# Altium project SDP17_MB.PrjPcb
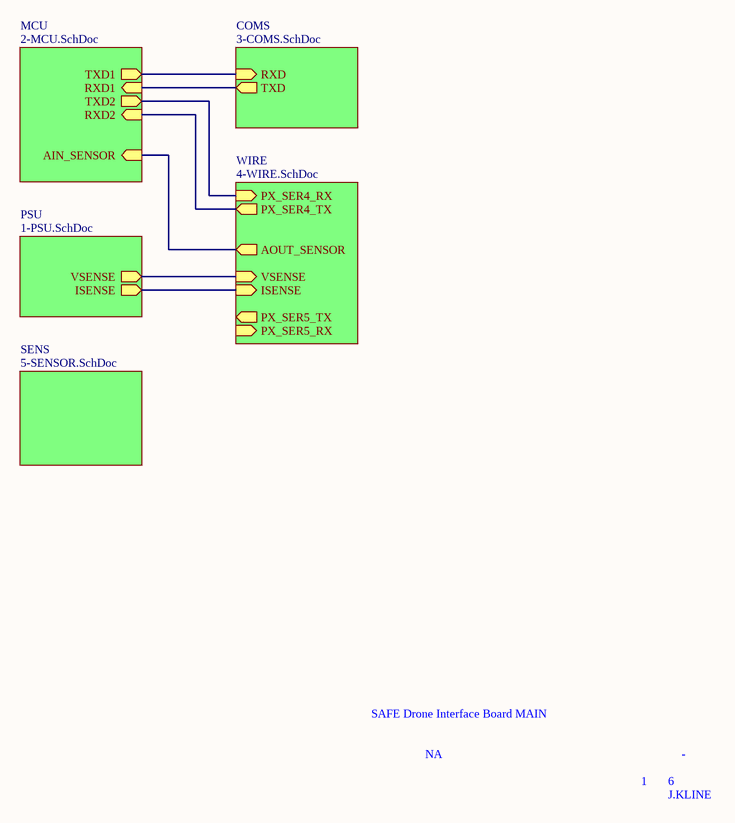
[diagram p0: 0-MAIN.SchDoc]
6 sheets, 82 parts. Net scope: hierarchical (ports join the sheet entries above them; power ports are global).
Board file: MB_rev0.PcbDoc
Sheets:
  0-MAIN.SchDoc
    MCU = 2-MCU.SchDoc
    COMS = 3-COMS.SchDoc
    PSU = 1-PSU.SchDoc
    WIRE = 4-WIRE.SchDoc
    SENS = 5-SENSOR.SchDoc

## Sheet 0-MAIN.SchDoc
size A

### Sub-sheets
COMS = 3-COMS.SchDoc: TXD (out), RXD (in)
MCU = 2-MCU.SchDoc: TXD1 (out), RXD1 (in), TXD2 (out), RXD2 (in), AIN_SENSOR (in)
PSU = 1-PSU.SchDoc: VSENSE (out), ISENSE (out)
SENS = 5-SENSOR.SchDoc: no entries
WIRE = 4-WIRE.SchDoc: PX_SER4_RX (in), PX_SER4_TX (out), PX_SER5_TX (out), PX_SER5_RX (in), ISENSE (in), VSENSE (in), AOUT_SENSOR (out)

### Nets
AIN_SENSOR: sheet MCU/AIN_SENSOR, sheet WIRE/AOUT_SENSOR
RXD1: sheet MCU/RXD1, sheet COMS/TXD
RXD2: sheet MCU/RXD2, sheet WIRE/PX_SER4_TX
TXD1: sheet MCU/TXD1, sheet COMS/RXD
TXD2: sheet MCU/TXD2, sheet WIRE/PX_SER4_RX
NetC18_1: sheet PSU/VSENSE, sheet WIRE/VSENSE
NetC19_1: sheet PSU/ISENSE, sheet WIRE/ISENSE

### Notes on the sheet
- SAFE Drone Interface Board MAIN
- NA
- 1
- 6
- -
- J.KLINE

## Sheet 2-MCU.SchDoc
size A3; DrawnBy: Jamie Kline; Organization: UMASS ECE
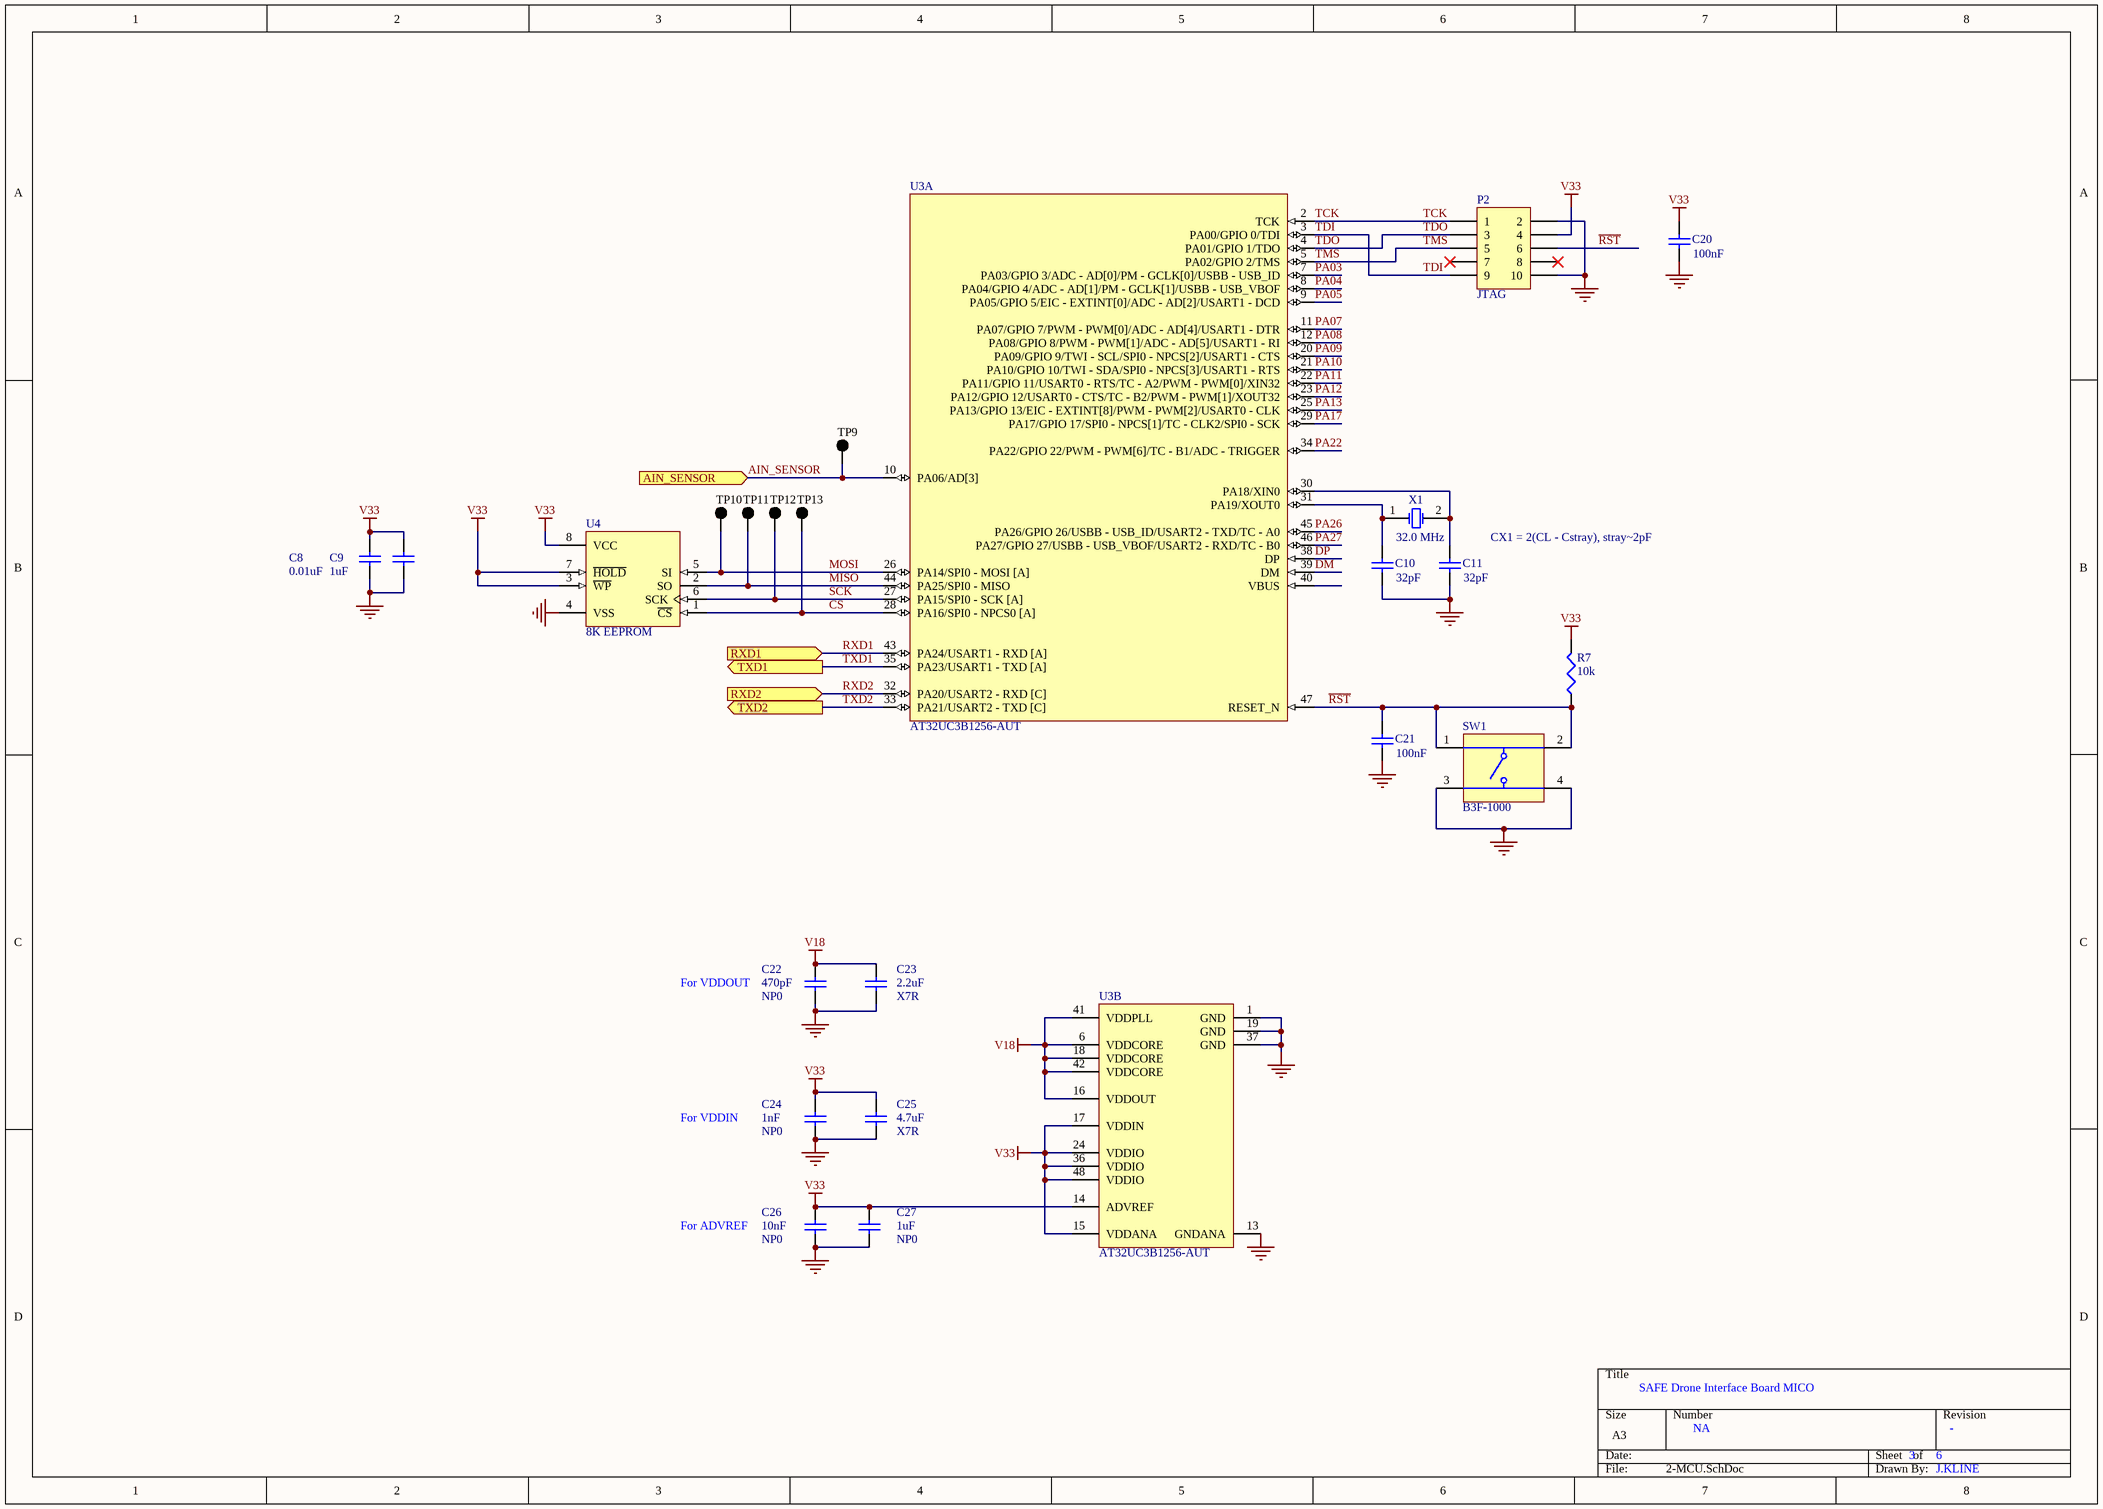
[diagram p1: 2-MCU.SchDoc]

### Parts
(Parts that share a designator on the sheet are numbered #1, #2 ... from top to bottom, then left to right.)
C8  value 0.01uF  [1608[0603]]  (hidden comment: Cap Semi)
C9  value 1uF  [1608[0603]]  (hidden comment: Cap Semi)
C10  value 32pF  [1608[0603]]  (hidden comment: Cap Semi)
C11  value 32pF  [1608[0603]]  (hidden comment: Cap Semi)
C20  value 100nF  [1608[0603]]  (hidden comment: Cap Semi)
C21  value 100nF  [1608[0603]]  (hidden comment: Cap Semi)
C22  value 470pF  Tempco: NP0  [1608[0603]]  (hidden comment: Cap Semi)
C23  value 2.2uF  Tempco: X7R  [1608[0603]]
C24  value 1nF  Tempco: NP0  [1608[0603]]  (hidden comment: Cap Semi)
C25  value 4.7uF  Tempco: X7R  [1608[0603]]
C26  value 10nF  Tempco: NP0  [1608[0603]]  (hidden comment: Cap Semi)
C27  value 1uF  Tempco: NP0  [1608[0603]]  (hidden comment: Cap Semi)
P2  JTAG  [HDR2X5]
R7  value 10k  [J1-0603]  (hidden comment: Res3)
SW1  B3F-1000  [OMRON-B3F-1000-4_V]
TP9#1  SENSOR  [KSTN-5011_V]  (value not drawn)
TP10  MOSI  [KSTN-5011_V]  (value not drawn)
TP11  MISO  [KSTN-5011_V]  (value not drawn)
TP12  SCK  [KSTN-5011_V]  (value not drawn)
TP13  CS  [KSTN-5011_V]  (value not drawn)
U3  AT32UC3B1256-AUT  [TQFP48_N]  (parts A,B of 2)
U4  8K EEPROM  [SOIC-SN8_N]
X1  Frequency: 32.0 MHz  [ABRA-ABLS2-2_V]  (hidden comment: ABLS2-32.000MHZ-D4YF-T)

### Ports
AIN_SENSOR (in), RXD1 (in), RXD2 (in), TXD1 (out), TXD2 (out)

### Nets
GND: C8.1 C9.2 C10.1 C11.1 C20.1 C21.1 C22.2 C23.1 C24.2 C25.1 C26.2 C27.2 P2.2 P2.10 SW1.3 SW1.4 U3.1(GND) U3.13(GNDANA) U3.19(GND) U3.37(GND) U4.4(VSS)
V18: C22.1 C23.2 U3.6(VDDCORE) U3.16(VDDOUT) U3.18(VDDCORE) U3.41(VDDPLL) U3.42(VDDCORE)
V33: C8.2 C9.1 C20.2 C24.1 C25.2 C26.1 C27.1 P2.4 R7.2 U3.14(ADVREF) U3.15(VDDANA) U3.17(VDDIN) U3.24(VDDIO) U3.36(VDDIO) U3.48(VDDIO) U4.3(~{WP}) U4.7(~{HOLD}) U4.8(VCC)
AIN_SENSOR: TP9#1.1 U3.10(PA06/AD[3]) ; port AIN_SENSOR
CS: TP13.1 U3.28(PA16/SPI0_-_NPCS0_[A]) U4.1(~{CS})
DM: U3.39(DM)
DP: U3.38(DP)
MISO: TP11.1 U3.44(PA25/SPI0_-_MISO) U4.2(SO)
MOSI: TP10.1 U3.26(PA14/SPI0_-_MOSI_[A]) U4.5(SI)
PA03: U3.7(PA03/GPIO_3/ADC_-_AD[0]/PM_-_GCLK[0]/USBB_-_USB_ID)
PA04: U3.8(PA04/GPIO_4/ADC_-_AD[1]/PM_-_GCLK[1]/USBB_-_USB_VBOF)
PA05: U3.9(PA05/GPIO_5/EIC_-_EXTINT[0]/ADC_-_AD[2]/USART1_-_DCD)
PA07: U3.11(PA07/GPIO_7/PWM_-_PWM[0]/ADC_-_AD[4]/USART1_-_DTR)
PA08: U3.12(PA08/GPIO_8/PWM_-_PWM[1]/ADC_-_AD[5]/USART1_-_RI)
PA09: U3.20(PA09/GPIO_9/TWI_-_SCL/SPI0_-_NPCS[2]/USART1_-_CTS)
PA10: U3.21(PA10/GPIO_10/TWI_-_SDA/SPI0_-_NPCS[3]/USART1_-_RTS)
PA11: U3.22(PA11/GPIO_11/USART0_-_RTS/TC_-_A2/PWM_-_PWM[0]/XIN32)
PA12: U3.23(PA12/GPIO_12/USART0_-_CTS/TC_-_B2/PWM_-_PWM[1]/XOUT32)
PA13: U3.25(PA13/GPIO_13/EIC_-_EXTINT[8]/PWM_-_PWM[2]/USART0_-_CLK)
PA17: U3.29(PA17/GPIO_17/SPI0_-_NPCS[1]/TC_-_CLK2/SPI0_-_SCK)
PA22: U3.34(PA22/GPIO_22/PWM_-_PWM[6]/TC_-_B1/ADC_-_TRIGGER)
PA26: U3.45(PA26/GPIO_26/USBB_-_USB_ID/USART2_-_TXD/TC_-_A0)
PA27: U3.46(PA27/GPIO_27/USBB_-_USB_VBOF/USART2_-_RXD/TC_-_B0)
~{RST}: C21.2 P2.6 R7.1 SW1.1 SW1.2 U3.47(RESET_N)
RXD1: U3.43(PA24/USART1_-_RXD_[A]) ; port RXD1
RXD2: U3.32(PA20/USART2_-_RXD_[C]) ; port RXD2
SCK: TP12.1 U3.27(PA15/SPI0_-_SCK_[A]) U4.6(SCK)
TCK: P2.1 U3.2(TCK)
TDI: P2.9 U3.3(PA00/GPIO_0/TDI)
TDO: P2.3 U3.4(PA01/GPIO_1/TDO)
TMS: P2.5 U3.5(PA02/GPIO_2/TMS)
TXD1: U3.35(PA23/USART1_-_TXD_[A]) ; port TXD1
TXD2: U3.33(PA21/USART2_-_TXD_[C]) ; port TXD2
NetC10_2: C10.2 U3.31(PA19/XOUT0) X1.1(X1)
NetC11_2: C11.2 U3.30(PA18/XIN0) X1.2(X2)

Not connected (* = marked no-connect by the designer): P2 7* 8*; U3 40(VBUS)

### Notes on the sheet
- (near C11) CX1 = 2(CL - Cstray), stray|pF
- For VDDOUT
- For VDDIN
- For ADVREF
- SAFE Drone Interface Board MICO
- NA
- 3
- 6
- -
- J.KLINE

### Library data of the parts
C8-C11 C20-C22 C24 C26 C27 = Cap Semi: Capacitor (Semiconductor SIM Model)
C23 C25 = Cap SMT: Capacitor (Semiconductor SIM Model)
P2 = Header 5X2: Header, 5-Pin, Dual row
R7 = Res3: Resistor
SW1 = CMP-1677-00002-1: Tactile Switch, SPST-NO, 0.05 A, 5 to 24 V, -25 to 70 degC, 4-Pin THD, RoHS, Bulk; Shielding: Shielded; Gender: Female; Capacitance: -45 f; Voltage Rating: 150 V; Current Rating: 1.5 A
TP9#1 TP10-TP13 = CMP-1672-00003-4: Test Point, Black, Through Hole, RoHS, Bulk; Manufacturer: Keystone
U3 = AT32UC3B1256-AUT: 32-bit AVR UC3 B Series Microcontroller, 256KB Flash, 32KB SRAM, 28 GPIO pins, Industrial Grade, 48-Pin TQFP, Tray
U4 = CMP-0165-00135-1: 8K SPI Bus Serial EEPROM, 8-Pin SOIC, Tape and Reel; Manufacture PN: CAT25080VI-GT3; ComponentAvailability: Unknown. Contact manufacturer to determine status.
X1 = CMP-0277-00002-1: Low Profile Surface Mount Microprocessor Crystal, 4.096 MHz +/-30 ppm, 180 Ohm, -40 to 85 degC, 2-Pin 11.4 x 4.7 x 3.3 mm SMD, RoHS, Tape and Reel; Manufacturer: Abracon; Operation Mode: Fundamental or 3rd Overtone; Shunt Capacitance: 7 pF Max.; ESR: 180 Ohm; Load Capacitance: 18 pF

## Sheet 3-COMS.SchDoc
size A
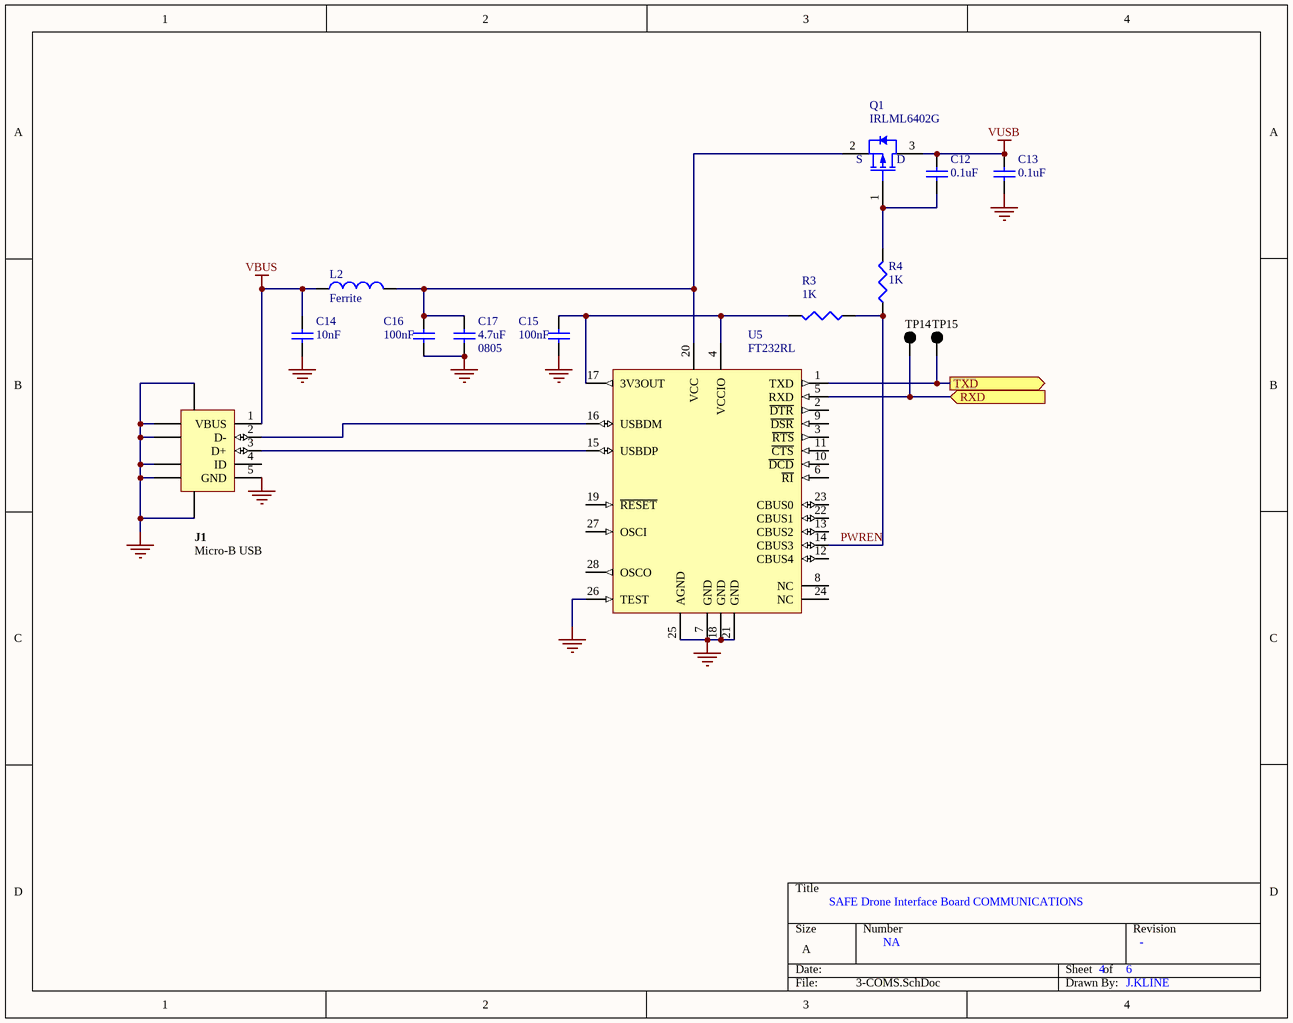
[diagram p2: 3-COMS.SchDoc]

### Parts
C12  value 0.1uF  [1608[0603]]  (hidden comment: Cap Semi)
C13  value 0.1uF  [1608[0603]]  (hidden comment: Cap Semi)
C14  value 10nF  [1608[0603]]  (hidden comment: Cap Semi)
C15  value 100nF  [1608[0603]]  (hidden comment: Cap Semi)
C16  value 100nF  [1608[0603]]  (hidden comment: Cap Semi)
C17  0805  value 4.7uF  [2012[0805]]
J1  Micro-B USB  [HIRO-ZX62R-B-5P_V]
L2  Ferrite  [INDC2013X105X50ML20T30]
Q1  IRLML6402G  [INTR-SOT-23-3_V]
R3  value 1K  [J1-0603]  (hidden comment: Res3)
R4  value 1K  [J1-0603]  (hidden comment: Res3)
TP14  RX  [KSTN-5011_V]  (value not drawn)
TP15  TX  [KSTN-5011_V]  (value not drawn)
U5  FT232RL  [SSOP-28_N]

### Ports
RXD (in), TXD (out)

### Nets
GND: C13.1 C14.1 C15.2 C16.1 C17.1 J1.5(GND) J1.6(SHLD) J1.7(SHLD) J1.8(SHLD) J1.9(SHLD) J1.10(SHLD) J1.11(SHLD) U5.7(GND) U5.18(GND) U5.21(GND) U5.25(AGND) U5.26(TEST)
VBUS: C14.2 J1.1(VBUS) L2.1
VUSB: C12.2 C13.2 Q1.3(D)
PWREN: R3.1 R4.1 U5.14(CBUS3)
RXD1: TP15.1 U5.1(TXD) ; port TXD
TXD1: TP14.1 U5.5(RXD) ; port RXD
NetC12_1: C12.1 Q1.1(G) R4.2
NetC15_1: C15.1 R3.2 U5.4(VCCIO) U5.17(3V3OUT)
NetC16_2: C16.2 C17.2 L2.2 Q1.2(S) U5.20(VCC)
NetJ1_2: J1.2(D-) U5.16(USBDM)
NetJ1_3: J1.3(D+) U5.15(USBDP)

Not connected (* = marked no-connect by the designer): J1 4(ID); U5 2(~{DTR}) 3(~{RTS}) 6(~{RI}) 8(NC) 9(~{DSR}) 10(~{DCD}) 11(~{CTS}) 12(CBUS4) 13(CBUS2) 19(~{RESET}) 22(CBUS1) 23(CBUS0) 24(NC) 27(OSCI) 28(OSCO)

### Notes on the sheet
- (near Q1) S
- (near Q1) D
- SAFE Drone Interface Board COMMUNICATIONS
- NA
- 4
- 6
- -
- J.KLINE

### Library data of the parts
C12-C16 = Cap Semi: Capacitor (Semiconductor SIM Model)
C17 = Cap SMT: Capacitor (Semiconductor SIM Model)
J1 = CMP-0031-00001-1: Connector; USBMicro-B,Reverse type, SMT; 5 Position; Right Angle; PartNumber: ZX62R-B-5P(30)
L2 = CMP-1660-00003-1: Chip Inductor, 21 Ohm, +/- 30%, 6 A, -40 to 125 degC, 0805 (2012 Metric), RoHS, Tape and Reel; Current Rating: 6 A; Resistance: 4 mohm; Case\Package: 0805; Impedance: 21 Ohm
Q1 = CMP-0676-00001-1: HEXFET Power MOSFET, P-Channel, -20 V VDSS, 0.065 Ohm RDS, 3-Pin SOT23, RoHS, Tape and Reel; PartNumber: IRLML6402GPbF; Manufacturer: International Rectifier; ISM (Max.): -22 A; QRR (Typ.): 11 nC; VSD (Max.): -1.2 V; IS (Max.): -1.3 A; VGS(TH): -0.4 to -1.2 V; V(BR)DSS (Min.): -20 V; TRR (Typ.): 29 ns
R3 R4 = Res3: Resistor
TP14 TP15 = CMP-1672-00003-4: as TP9#1 on sheet 2-MCU
U5 = CMP-0078-00028-3: USB UART Asynchronous Serial Data Transfer Chip, 28-pin SSOP, Tube; PartNumber: FT232RL-Tube; Manufacturer: FTDI

## Sheet 1-PSU.SchDoc
size A
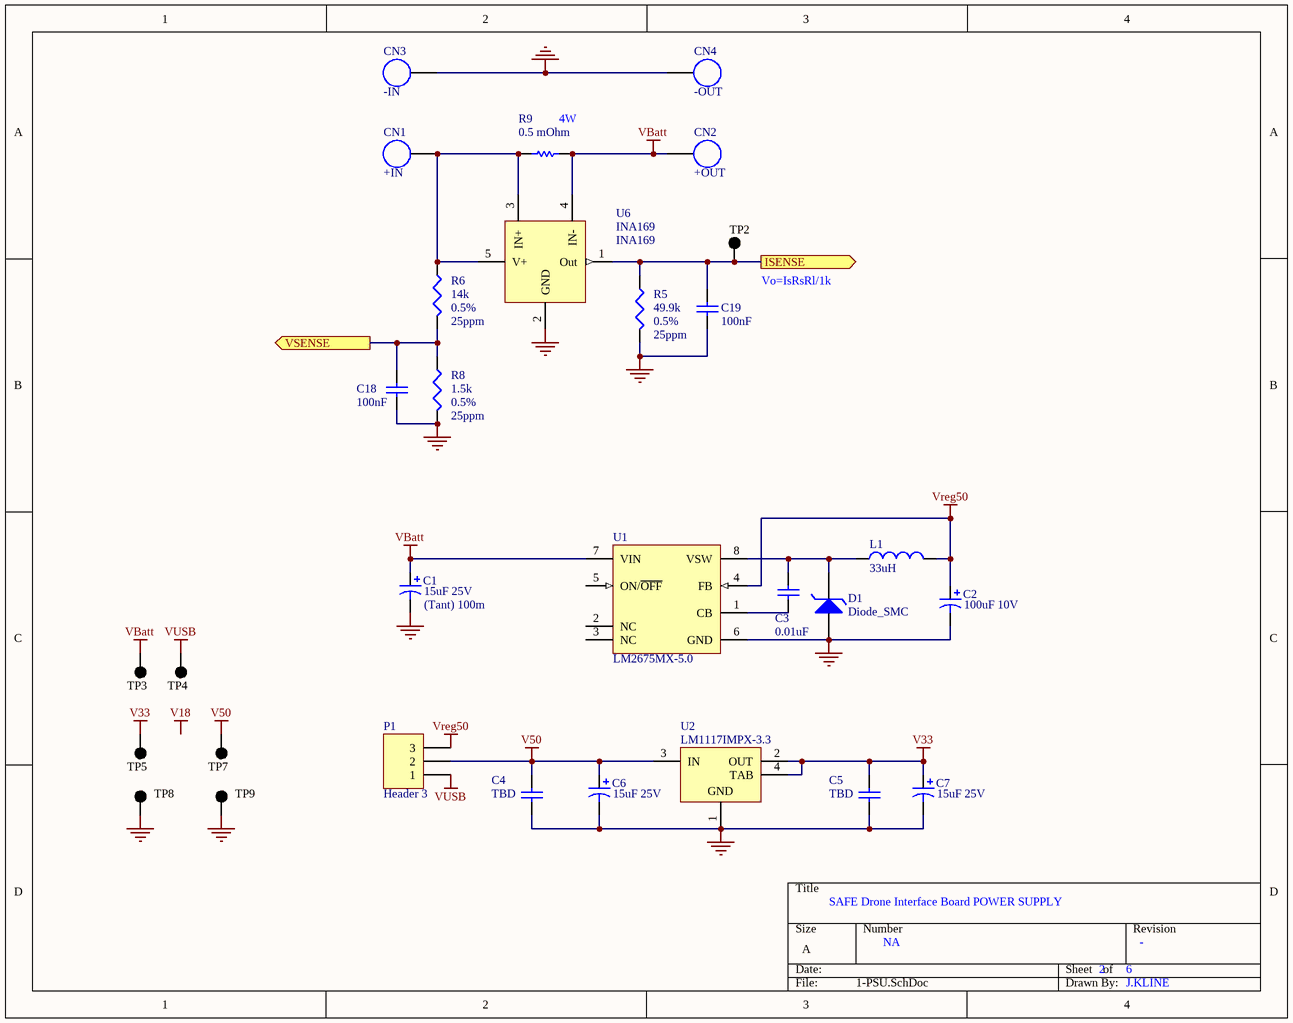
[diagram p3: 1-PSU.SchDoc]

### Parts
(Parts that share a designator on the sheet are numbered #1, #2 ... from top to bottom, then left to right.)
C1  15uF 25V  [AVX-CAPC7343_V]
C2  100uF 10V  [AVX-CAPC7343_V]
C3  value 0.01uF  [1608[0603]]  (hidden comment: Cap Semi)
C4  value TBD  [1608[0603]]  (hidden comment: Cap Semi)
C5  value TBD  [1608[0603]]  (hidden comment: Cap Semi)
C6  15uF 25V  [AVX-CAPC7343_V]
C7  15uF 25V  [AVX-CAPC7343_V]
C18  value 100nF  [1608[0603]]  (hidden comment: Cap Semi)
C19  value 100nF  [1608[0603]]  (hidden comment: Cap Semi)
CN1  +IN  [WireConn_120mil]
CN2  +OUT  [WireConn_120mil]
CN3  -IN  [WireConn_120mil]
CN4  -OUT  [WireConn_120mil]
D1  Diode_SMC  [SMC]
L1  Supplier Part Number 1: 33uH  [IND_TOROID_SMT_PULSE]  (hidden comment: PE-53823SNL)
P1  Header 3  [HDR1X3]
R5  value 49.9k  Tol: 0.5%  Tempco: 25ppm  [J1-0603]  (hidden comment: Res3)
R6  value 14k  Tol: 0.5%  Tempco: 25ppm  [J1-0603]  (hidden comment: Res3)
R8  value 1.5k  Tol: 0.5%  Tempco: 25ppm  [J1-0603]  (hidden comment: Res3)
R9  Resistance: 0.5 mOhm  [STAC-CSS2725-099H_V]  (hidden comment: CSS2725FTL500CT-ND)
TP2  ISENSE  [KSTN-5011_V]  (value not drawn)
TP3  VBatt  [KSTN-5011_V]  (value not drawn)
TP4  VUSB  [KSTN-5011_V]  (value not drawn)
TP5  V33  [KSTN-5011_V]  (value not drawn)
TP7  V50  [KSTN-5011_V]  (value not drawn)
TP8  GND  [KSTN-5011_V]  (value not drawn)
TP9#2  GND  [KSTN-5011_V]  (value not drawn)
U1  LM2675MX-5.0  [M08A_L]
U2  LM1117IMPX-3.3  [MP04A_M]
U6  INA169  [SOT23-5BL]

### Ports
ISENSE (out), VSENSE (out)

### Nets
GND: C1.2 C2.2 C4.1 C5.1 C6.2 C7.2 C18.2 C19.2 CN3.1 CN4.1 D1.1(A) R5.2 R8.2 TP8.1 TP9#2.1 U1.6(GND) U2.1(GND) U6.2(GND)
V33: C5.2 C7.1 TP5.1 U2.2(OUT) U2.4(TAB)
V50: C4.2 C6.1 P1.2 TP7.1 U2.3(IN)
VBatt: C1.1 CN2.1 R9.2 TP3.1 U1.7(VIN) U6.4(IN-)
Vreg50: C2.1 L1.2 P1.3 U1.4(FB)
VUSB: P1.1 TP4.1
NetC3_1: C3.1 D1.2(K) L1.1 U1.8(VSW)
NetC3_2: C3.2 U1.1(CB)
NetC18_1: C18.1 R6.2 R8.1 ; port VSENSE
NetC19_1: C19.1 R5.1 TP2.1 U6.1(Out) ; port ISENSE
NetCN1_1: CN1.1 R6.1 R9.1 U6.3(IN+) U6.5(V+)

Not connected (* = marked no-connect by the designer): U1 2(NC) 3(NC) 5(ON/~{OFF})

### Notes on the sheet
- (near R9) 4W
- Vo=IsRsRl/1k
- (near C1) (Tant) 100m
- SAFE Drone Interface Board POWER SUPPLY
- NA
- 2
- 6
- -
- J.KLINE
- Labels drawn without touching a wire or pin: V18

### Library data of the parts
C1 C6 C7 = CMP-0279-00002-2: 15µF ±10% Molded Tantalum Capacitors 25V 2312 (6032 Metric) 100 mOhm; PartNumber: TPSD156K025S0100; Manufacturer: AVX; Polarity: Polarized
C2 = CMP-0279-00002-2: 15µF ±10% Molded Tantalum Capacitors 10V 2312 (6032 Metric) 50 mOhm; PartNumber: TPSD156K025S0100; Manufacturer: AVX; Polarity: Polarized
C3-C5 C18 C19 = Cap Semi: Capacitor (Semiconductor SIM Model)
CN1-CN4 = Wire_Conn_Batt
D1 = Diode_SMC: DO-214-AB / SMC SCHOTTKY
L1 = PE-53823SNL: FIXED IND 38UH 1.2A 100 MOHM SMD; Manufacturer: Pulse Electronics Corporation; Type: Toroidal; Inductance: 38µH; Shielding: Unshielded
P1 = Header 3: Header, 3-Pin
R5 R6 R8 = Res3: Resistor
R9 = CMP-1719-00001-2: Chip Resistor, 0.5 mOhm, +/- 1%, 4 W, -55 to 225 degC, 2725 (6865 Metric), RoHS, Tape and Reel
TP2-TP5 TP7 TP8 TP9#2 = CMP-1672-00003-4: as TP9#1 on sheet 2-MCU
U1 = CMP-0069-00673-2: SIMPLE SWITCHER® Power Converter High Efficiency 1A Step-Down Voltage Regulator, 8-pin Narrow SOIC; Manufacturer: National Semiconductor; PowerWise: N; PackageTopMarking: NSZXTT*2675*M5.0
U2 = CMP-0062-01630-3: 800mA Low-Dropout Linear Regulator, 4-pin SOT-223; Manufacturer: National Semiconductor; CompType: LDO IC; PowerWise: N; High-Reliability: Y; PackageTopMarking: XYTT*N05B
U6 = INA169: Manufacturer: Texas Instruments; Manufacturer Part Number: INA169NA/250; Function: Current Monitor; Sensing Method: High-Side; Accuracy: ±0.5%; Voltage - Input: 2.7 V ~ 60 V

## Sheet 4-WIRE.SchDoc
size A
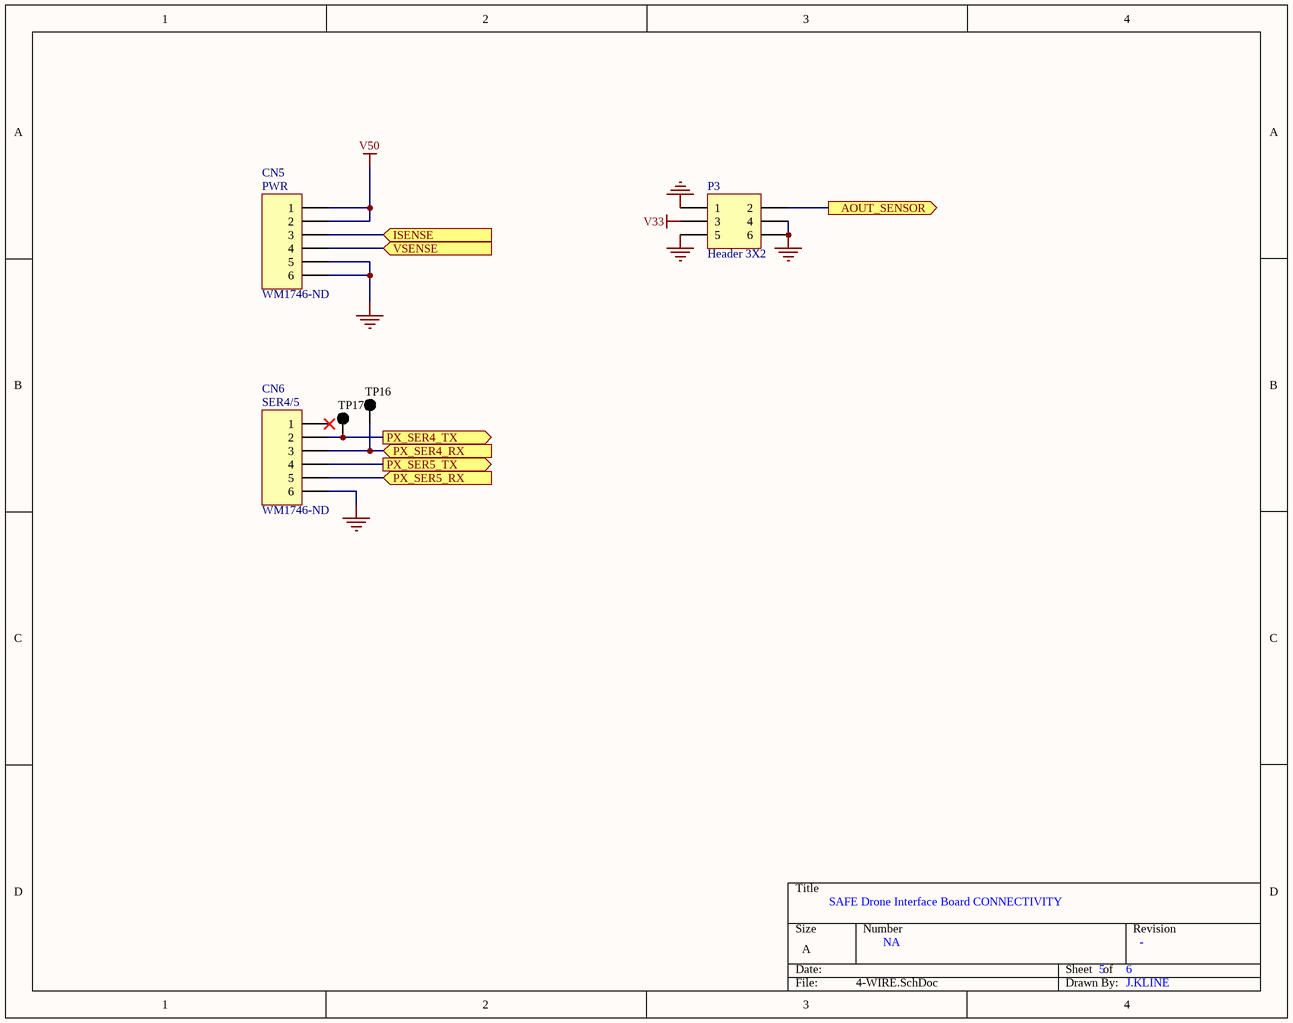
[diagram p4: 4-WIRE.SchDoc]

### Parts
CN5  PWR  Supplier Part Number 1: WM1746-ND  [CONN_PICOBLADE_6P]
CN6  SER4/5  Supplier Part Number 1: WM1746-ND  [CONN_PICOBLADE_6P]
P3  Header 3X2  [HDR2X3]
TP16  RX  [KSTN-5011_V]  (value not drawn)
TP17  TX  [KSTN-5011_V]  (value not drawn)

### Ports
AOUT_SENSOR (out), ISENSE (in), PX_SER4_RX (in), PX_SER4_TX (out), PX_SER5_RX (in), PX_SER5_TX (out), VSENSE (in)

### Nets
GND: CN5.5 CN5.6 CN6.6 P3.1 P3.4 P3.5 P3.6
V33: P3.3
V50: CN5.1 CN5.2
AIN_SENSOR: P3.2 ; port AOUT_SENSOR
RXD2: CN6.2 TP17.1 ; port PX_SER4_TX
TXD2: CN6.3 TP16.1 ; port PX_SER4_RX
NetC18_1: CN5.4 ; port VSENSE
NetC19_1: CN5.3 ; port ISENSE
NetCN6_4: CN6.4 ; port PX_SER5_TX
NetCN6_5: CN6.5 ; port PX_SER5_RX

Not connected (* = marked no-connect by the designer): CN6 1*

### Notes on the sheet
- SAFE Drone Interface Board CONNECTIVITY
- NA
- 5
- 6
- -
- J.KLINE

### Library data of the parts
CN5 CN6 = CONN_PicoBlade_6P_RA: PicoBlade right angle through hole conn; Manufacturer: Molex, LLC; Manufacturer Part Number: 0530480610; Connector Type: Header; Pitch - Mating: 0.049" (1.25mm); Shrouding: Shrouded - 4 Wall; Number of Positions: 6; Number of Positions Loaded: All
P3 = Header 3X2: Header, 3-Pin, Dual row
TP16 TP17 = CMP-1672-00003-4: as TP9#1 on sheet 2-MCU

## Sheet 5-SENSOR.SchDoc
size A
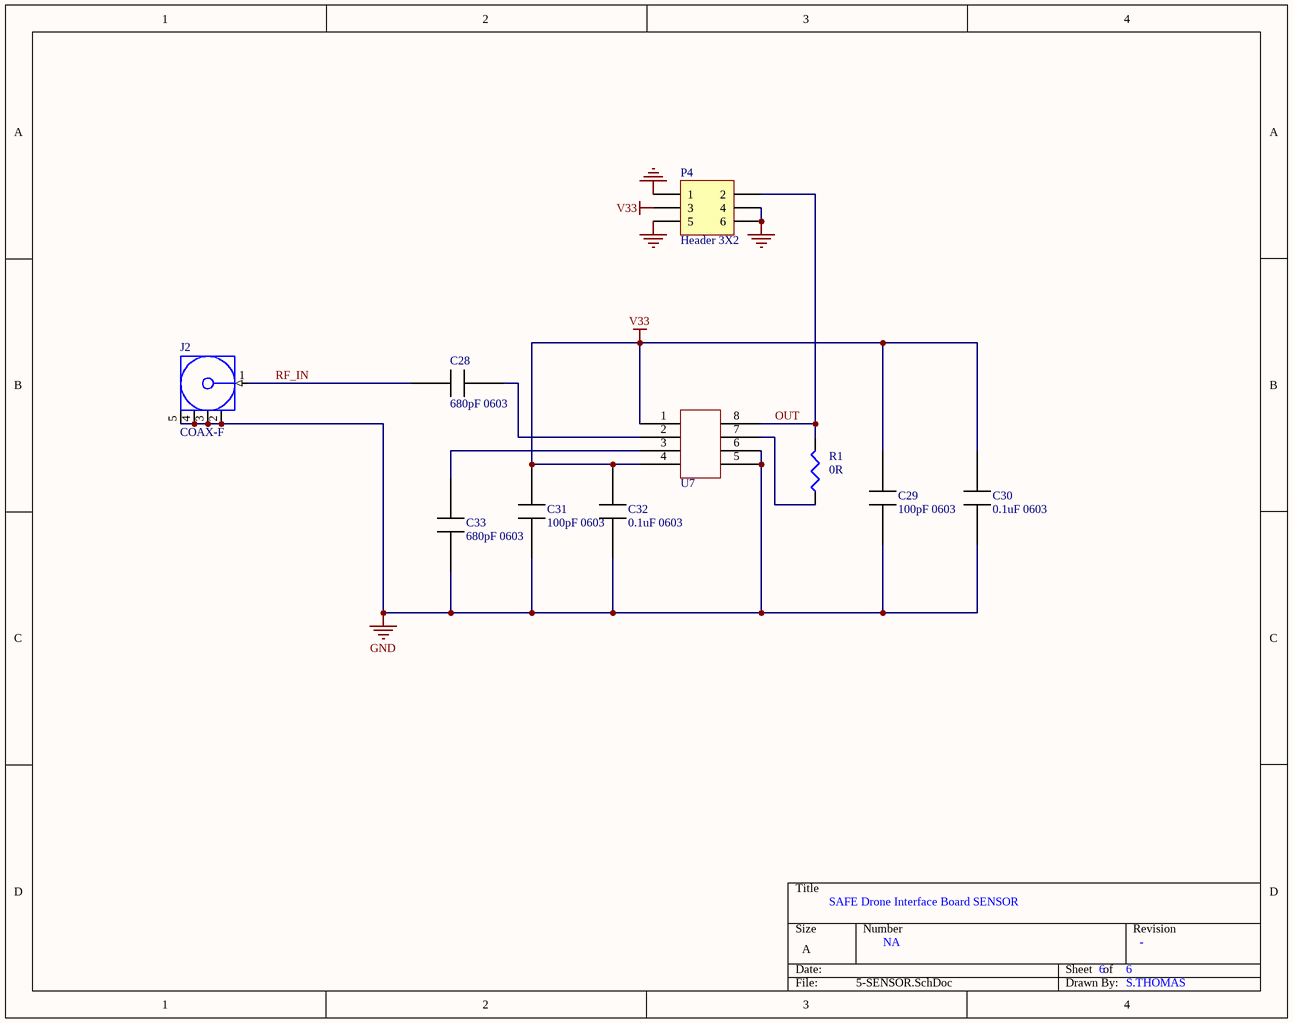
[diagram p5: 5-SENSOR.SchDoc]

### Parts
C28  680pF 0603  [CAP 680pF 0603]
C29  100pF 0603  [Surface mnt capacitor]
C30  0.1uF 0603  [Surface mnt Cap]
C31  100pF 0603  [Surface mnt capacitor]
C32  0.1uF 0603  [Surface mnt Cap]
C33  680pF 0603  [CAP 680pF 0603]
J2  COAX-F  [MCX5.08-H5]
P4  Header 3X2  [HDR2X3]
R1  value 0R  [J1-0603]  (hidden comment: Res3)
U7  MAX2015  [TSOP65P490X110-8N]  (value not drawn)

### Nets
GND: C29.2 C30.1 C31.1 C32.1 C33.1 J2.2(GND) J2.3(GND) J2.4(GND) J2.5(GND) P4.1 P4.4 P4.5 P4.6 U7.5 U7.6
V33: C29.1 C30.2 C31.2 C32.2 P4.3 U7.1 U7.4
OUT: P4.2 R1.2 U7.8
RF_IN: C28.1 J2.1(Signal)
NetC28_2: C28.2 U7.2
NetC33_2: C33.2 U7.3
NetR1_1: R1.1 U7.7

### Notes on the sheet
- SAFE Drone Interface Board SENSOR
- NA
- 6
- -
- S.THOMAS

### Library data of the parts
C28 C33 = Surface Mount Cap: Surface Mount Capacitor
C29 C31 = Surface mnt cap 100pF
J2 = COAX-F: RF Coaxial PCB Connector, MCX; Thru-Hole, Right-Angle Mount Socket, Blunt Post Terminal, 50 Ohm Impedance; PCB_Layout: Complies with manufacturer's recommendation.; DrillSize: Corresponds to nominal value.
P4 = Header 3X2: Header, 3-Pin, Dual row
R1 = Res3: Resistor
U7 = MAX2015: IC

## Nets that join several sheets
GND: 2-MCU (21 pins), 3-COMS (17 pins), 1-PSU (18 pins), 4-WIRE (7 pins), 5-SENSOR (15 pins)
V33: 2-MCU (18 pins), 1-PSU (5 pins), 4-WIRE (P3.3), 5-SENSOR (7 pins)
V50: 1-PSU (5 pins), 4-WIRE (CN5.1 CN5.2)
VUSB: 3-COMS (C12.2 C13.2 Q1.3), 1-PSU (P1.1 TP4.1)
AIN_SENSOR: 2-MCU (TP9#1.1 U3.10), 4-WIRE (P3.2)
NetC18_1: 1-PSU (C18.1 R6.2 R8.1), 4-WIRE (CN5.4)
NetC19_1: 1-PSU (C19.1 R5.1 TP2.1 U6.1), 4-WIRE (CN5.3)
RXD1: 2-MCU (U3.43), 3-COMS (TP15.1 U5.1)
RXD2: 2-MCU (U3.32), 4-WIRE (CN6.2 TP17.1)
TXD1: 2-MCU (U3.35), 3-COMS (TP14.1 U5.5)
TXD2: 2-MCU (U3.33), 4-WIRE (CN6.3 TP16.1)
